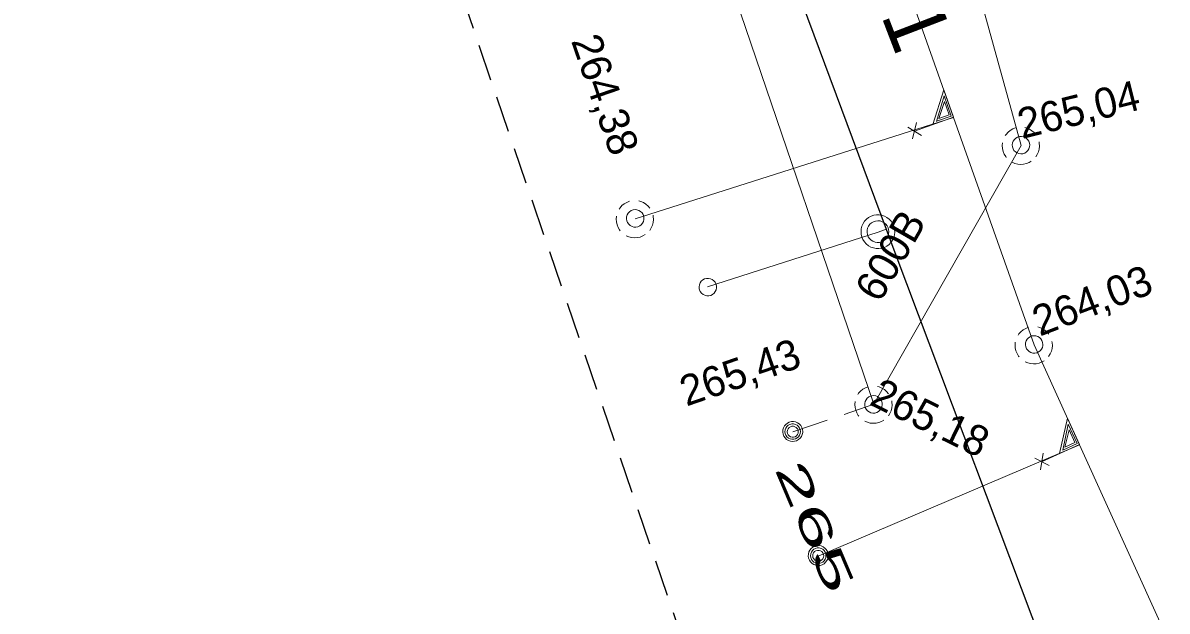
# Model space of a CAD drawing. Extents: x -732074 to -731966, y -1048695 to -1047982.
# Drawn here: x -732074 to -732043.73, y -1048462.87 to -1048447.33 of the extents above; entities that cross this region are included whole.
import ezdxf

# ---------------------------------------------------------------- set-up
doc = ezdxf.new("R2010")
doc.units = 0
doc.header["$LTSCALE"] = 0.32
doc.linetypes.add('MEDIUM_DASHED', pattern=[4.5, 3, -1.5])
doc.layers.add('1', color=7, linetype='Continuous')
for name, color, linetype, lineweight in [('18', 7, 'Continuous', 13), ('20', 7, 'Continuous', 13), ('49', 7, 'Continuous', 13), ('63', 7, 'MEDIUM_DASHED', 25), ('8', 7, 'Continuous', 13)]:
    doc.layers.add(name, color=color, linetype=linetype, lineweight=lineweight)

msp = doc.modelspace()

# ---------------------------------------------------------------- linework, layer by layer
at = {"layer": '18'}
for p, q in [((-732050.591, -1048450.086), (-732050.226, -1048450.312)), ((-732050.466, -1048450.401), (-732050.36, -1048449.97)), ((-732047.235, -1048458.835), (-732046.852, -1048459.029)), ((-732047.083, -1048459.139), (-732047.014, -1048458.7))]:
    msp.add_line(p, q, dxfattribs=at)
for points in [[(-732050.416, -1048450.195), (-732049.383, -1048449.829), (-732049.641, -1048449.102), (-732049.928, -1048450.022)], [(-732049.833, -1048449.934), (-732049.441, -1048449.795), (-732049.63, -1048449.263), (-732049.834, -1048449.935)], [(-732049.77, -1048449.862), (-732049.496, -1048449.765), (-732049.62, -1048449.415), (-732049.769, -1048449.864)], [(-732047.743, -1048450.107), (-732047.814, -1048450.135), (-732047.88, -1048450.174), (-732047.941, -1048450.222), (-732047.992, -1048450.279), (-732048.016, -1048450.313)], [(-732047.201, -1048450.29), (-732047.252, -1048450.232), (-732047.309, -1048450.182), (-732047.375, -1048450.141), (-732047.446, -1048450.112), (-732047.495, -1048450.098)], [(-732048.088, -1048450.499), (-732048.093, -1048450.576), (-732048.088, -1048450.653), (-732048.071, -1048450.728), (-732048.043, -1048450.799), (-732048.002, -1048450.865), (-732047.987, -1048450.887)], [(-732047.206, -1048450.876), (-732047.166, -1048450.811), (-732047.135, -1048450.741), (-732047.115, -1048450.666), (-732047.108, -1048450.59), (-732047.113, -1048450.513), (-732047.119, -1048450.478)], [(-732047.83, -1048451.016), (-732047.76, -1048451.047), (-732047.684, -1048451.066), (-732047.608, -1048451.073), (-732047.532, -1048451.068), (-732047.456, -1048451.051), (-732047.385, -1048451.023), (-732047.325, -1048450.988)], [(-732057.953, -1048452.047), (-732058.024, -1048452.075), (-732058.091, -1048452.114), (-732058.151, -1048452.162), (-732058.202, -1048452.219), (-732058.226, -1048452.253)], [(-732057.412, -1048452.23), (-732057.462, -1048452.172), (-732057.52, -1048452.122), (-732057.585, -1048452.081), (-732057.656, -1048452.052), (-732057.705, -1048452.038)], [(-732058.298, -1048452.439), (-732058.304, -1048452.516), (-732058.299, -1048452.593), (-732058.282, -1048452.668), (-732058.253, -1048452.739), (-732058.213, -1048452.805), (-732058.197, -1048452.827)], [(-732057.417, -1048452.816), (-732057.376, -1048452.751), (-732057.345, -1048452.681), (-732057.326, -1048452.606), (-732057.318, -1048452.53), (-732057.323, -1048452.453), (-732057.329, -1048452.418)], [(-732058.04, -1048452.956), (-732057.97, -1048452.987), (-732057.895, -1048453.006), (-732057.819, -1048453.013), (-732057.742, -1048453.008), (-732057.667, -1048452.991), (-732057.595, -1048452.963), (-732057.535, -1048452.928)], [(-732047.403, -1048455.377), (-732047.474, -1048455.405), (-732047.541, -1048455.444), (-732047.601, -1048455.492), (-732047.652, -1048455.549), (-732047.676, -1048455.583)], [(-732046.862, -1048455.56), (-732046.912, -1048455.502), (-732046.97, -1048455.452), (-732047.035, -1048455.411), (-732047.106, -1048455.382), (-732047.155, -1048455.368)], [(-732047.748, -1048455.769), (-732047.754, -1048455.846), (-732047.749, -1048455.923), (-732047.732, -1048455.998), (-732047.703, -1048456.069), (-732047.663, -1048456.135), (-732047.647, -1048456.157)], [(-732046.867, -1048456.146), (-732046.826, -1048456.081), (-732046.795, -1048456.011), (-732046.776, -1048455.936), (-732046.768, -1048455.86), (-732046.773, -1048455.783), (-732046.779, -1048455.748)], [(-732047.49, -1048456.286), (-732047.42, -1048456.317), (-732047.345, -1048456.336), (-732047.269, -1048456.343), (-732047.192, -1048456.338), (-732047.117, -1048456.321), (-732047.045, -1048456.293), (-732046.985, -1048456.258)], [(-732051.642, -1048456.947), (-732051.713, -1048456.975), (-732051.779, -1048457.014), (-732051.84, -1048457.062), (-732051.891, -1048457.119), (-732051.914, -1048457.153)], [(-732051.1, -1048457.13), (-732051.151, -1048457.072), (-732051.208, -1048457.022), (-732051.274, -1048456.981), (-732051.345, -1048456.952), (-732051.394, -1048456.938)], [(-732051.987, -1048457.339), (-732051.992, -1048457.416), (-732051.987, -1048457.493), (-732051.97, -1048457.568), (-732051.941, -1048457.639), (-732051.901, -1048457.705), (-732051.886, -1048457.727)], [(-732051.105, -1048457.716), (-732051.065, -1048457.651), (-732051.034, -1048457.581), (-732051.014, -1048457.506), (-732051.007, -1048457.43), (-732051.012, -1048457.353), (-732051.017, -1048457.318)], [(-732051.728, -1048457.856), (-732051.659, -1048457.887), (-732051.583, -1048457.906), (-732051.507, -1048457.913), (-732051.431, -1048457.908), (-732051.355, -1048457.891), (-732051.284, -1048457.863), (-732051.223, -1048457.828)], [(-732047.051, -1048458.929), (-732046.053, -1048458.475), (-732046.372, -1048457.773), (-732046.579, -1048458.714)], [(-732046.493, -1048458.619), (-732046.114, -1048458.447), (-732046.348, -1048457.933), (-732046.494, -1048458.619)], [(-732046.436, -1048458.541), (-732046.171, -1048458.421), (-732046.325, -1048458.083), (-732046.435, -1048458.543)]]:
    msp.add_lwpolyline(points, dxfattribs=at)
for points in [[(-732047.484, -1048450.364), (-732047.532, -1048450.343), (-732047.585, -1048450.334), (-732047.637, -1048450.336), (-732047.688, -1048450.351), (-732047.733, -1048450.377), (-732047.772, -1048450.412), (-732047.802, -1048450.455), (-732047.822, -1048450.504), (-732047.83, -1048450.556), (-732047.825, -1048450.609), (-732047.809, -1048450.659), (-732047.783, -1048450.703), (-732047.746, -1048450.742), (-732047.702, -1048450.77), (-732047.653, -1048450.789), (-732047.601, -1048450.794), (-732047.549, -1048450.79), (-732047.498, -1048450.772), (-732047.455, -1048450.744), (-732047.417, -1048450.707), (-732047.39, -1048450.663), (-732047.373, -1048450.612), (-732047.368, -1048450.56), (-732047.375, -1048450.508), (-732047.394, -1048450.459), (-732047.423, -1048450.415), (-732047.461, -1048450.379)], [(-732057.569, -1048452.499), (-732057.575, -1048452.447), (-732057.593, -1048452.397), (-732057.621, -1048452.353), (-732057.659, -1048452.316), (-732057.704, -1048452.289), (-732057.754, -1048452.273), (-732057.806, -1048452.268), (-732057.858, -1048452.275), (-732057.907, -1048452.294), (-732057.951, -1048452.324), (-732057.986, -1048452.363), (-732058.012, -1048452.408), (-732058.027, -1048452.459), (-732058.03, -1048452.511), (-732058.022, -1048452.563), (-732058.001, -1048452.611), (-732057.971, -1048452.654), (-732057.931, -1048452.689), (-732057.885, -1048452.713), (-732057.834, -1048452.727), (-732057.782, -1048452.729), (-732057.73, -1048452.719), (-732057.682, -1048452.697), (-732057.64, -1048452.665), (-732057.607, -1048452.625), (-732057.583, -1048452.578), (-732057.571, -1048452.527)], [(-732047.019, -1048455.829), (-732047.025, -1048455.777), (-732047.043, -1048455.727), (-732047.071, -1048455.683), (-732047.109, -1048455.646), (-732047.154, -1048455.619), (-732047.204, -1048455.603), (-732047.256, -1048455.598), (-732047.308, -1048455.605), (-732047.357, -1048455.624), (-732047.401, -1048455.654), (-732047.436, -1048455.693), (-732047.462, -1048455.738), (-732047.477, -1048455.789), (-732047.48, -1048455.841), (-732047.472, -1048455.893), (-732047.451, -1048455.941), (-732047.421, -1048455.984), (-732047.381, -1048456.019), (-732047.335, -1048456.043), (-732047.284, -1048456.057), (-732047.232, -1048456.059), (-732047.18, -1048456.049), (-732047.132, -1048456.027), (-732047.09, -1048455.995), (-732047.057, -1048455.955), (-732047.033, -1048455.908), (-732047.021, -1048455.857)], [(-732051.573, -1048457.194), (-732051.62, -1048457.217), (-732051.662, -1048457.25), (-732051.694, -1048457.291), (-732051.717, -1048457.339), (-732051.728, -1048457.39), (-732051.727, -1048457.442), (-732051.715, -1048457.493), (-732051.692, -1048457.54), (-732051.658, -1048457.58), (-732051.615, -1048457.612), (-732051.567, -1048457.633), (-732051.516, -1048457.643), (-732051.463, -1048457.641), (-732051.413, -1048457.627), (-732051.366, -1048457.602), (-732051.328, -1048457.567), (-732051.297, -1048457.525), (-732051.276, -1048457.476), (-732051.268, -1048457.424), (-732051.272, -1048457.371), (-732051.287, -1048457.322), (-732051.313, -1048457.276), (-732051.349, -1048457.237), (-732051.393, -1048457.208), (-732051.441, -1048457.19), (-732051.494, -1048457.182), (-732051.546, -1048457.187)], [(-732053.371, -1048458.129), (-732053.377, -1048458.073), (-732053.394, -1048458.02), (-732053.423, -1048457.971), (-732053.461, -1048457.93), (-732053.507, -1048457.898), (-732053.559, -1048457.876), (-732053.614, -1048457.865), (-732053.67, -1048457.867), (-732053.725, -1048457.88), (-732053.776, -1048457.905), (-732053.82, -1048457.94), (-732053.856, -1048457.983), (-732053.881, -1048458.033), (-732053.896, -1048458.088), (-732053.899, -1048458.144), (-732053.89, -1048458.199), (-732053.869, -1048458.252), (-732053.838, -1048458.298), (-732053.798, -1048458.337), (-732053.75, -1048458.367), (-732053.697, -1048458.386), (-732053.641, -1048458.393), (-732053.585, -1048458.389), (-732053.531, -1048458.372), (-732053.482, -1048458.345), (-732053.44, -1048458.307), (-732053.407, -1048458.262), (-732053.384, -1048458.211), (-732053.372, -1048458.156)], [(-732053.43, -1048458.132), (-732053.436, -1048458.083), (-732053.454, -1048458.037), (-732053.482, -1048457.996), (-732053.519, -1048457.963), (-732053.563, -1048457.941), (-732053.611, -1048457.929), (-732053.66, -1048457.929), (-732053.708, -1048457.941), (-732053.752, -1048457.964), (-732053.789, -1048457.997), (-732053.817, -1048458.038), (-732053.834, -1048458.085), (-732053.84, -1048458.134), (-732053.833, -1048458.183), (-732053.815, -1048458.229), (-732053.787, -1048458.269), (-732053.75, -1048458.302), (-732053.706, -1048458.324), (-732053.657, -1048458.336), (-732053.608, -1048458.335), (-732053.56, -1048458.323), (-732053.517, -1048458.299), (-732053.48, -1048458.266), (-732053.452, -1048458.225), (-732053.436, -1048458.178)], [(-732053.489, -1048458.136), (-732053.495, -1048458.094), (-732053.512, -1048458.056), (-732053.54, -1048458.025), (-732053.575, -1048458.002), (-732053.615, -1048457.991), (-732053.657, -1048457.991), (-732053.697, -1048458.003), (-732053.732, -1048458.026), (-732053.759, -1048458.058), (-732053.776, -1048458.096), (-732053.781, -1048458.137), (-732053.775, -1048458.179), (-732053.757, -1048458.216), (-732053.729, -1048458.248), (-732053.693, -1048458.27), (-732053.653, -1048458.281), (-732053.611, -1048458.28), (-732053.571, -1048458.267), (-732053.537, -1048458.244), (-732053.51, -1048458.211), (-732053.494, -1048458.173)], [(-732052.696, -1048461.407), (-732052.701, -1048461.351), (-732052.718, -1048461.298), (-732052.747, -1048461.249), (-732052.786, -1048461.208), (-732052.831, -1048461.176), (-732052.884, -1048461.154), (-732052.939, -1048461.143), (-732052.995, -1048461.145), (-732053.049, -1048461.158), (-732053.1, -1048461.183), (-732053.145, -1048461.218), (-732053.181, -1048461.261), (-732053.206, -1048461.311), (-732053.221, -1048461.366), (-732053.223, -1048461.422), (-732053.215, -1048461.477), (-732053.194, -1048461.53), (-732053.163, -1048461.576), (-732053.122, -1048461.615), (-732053.075, -1048461.645), (-732053.022, -1048461.664), (-732052.966, -1048461.671), (-732052.909, -1048461.667), (-732052.855, -1048461.65), (-732052.806, -1048461.623), (-732052.765, -1048461.585), (-732052.732, -1048461.54), (-732052.708, -1048461.489), (-732052.696, -1048461.434)], [(-732052.755, -1048461.41), (-732052.761, -1048461.361), (-732052.779, -1048461.315), (-732052.806, -1048461.274), (-732052.843, -1048461.241), (-732052.887, -1048461.219), (-732052.936, -1048461.207), (-732052.985, -1048461.207), (-732053.032, -1048461.219), (-732053.076, -1048461.242), (-732053.114, -1048461.275), (-732053.142, -1048461.316), (-732053.159, -1048461.363), (-732053.164, -1048461.412), (-732053.157, -1048461.461), (-732053.14, -1048461.507), (-732053.112, -1048461.547), (-732053.075, -1048461.58), (-732053.031, -1048461.602), (-732052.982, -1048461.614), (-732052.933, -1048461.613), (-732052.885, -1048461.601), (-732052.842, -1048461.577), (-732052.804, -1048461.544), (-732052.777, -1048461.503), (-732052.761, -1048461.456)], [(-732052.814, -1048461.414), (-732052.82, -1048461.372), (-732052.837, -1048461.334), (-732052.865, -1048461.303), (-732052.899, -1048461.28), (-732052.94, -1048461.269), (-732052.982, -1048461.269), (-732053.022, -1048461.281), (-732053.056, -1048461.304), (-732053.083, -1048461.336), (-732053.1, -1048461.374), (-732053.105, -1048461.415), (-732053.1, -1048461.457), (-732053.081, -1048461.494), (-732053.054, -1048461.526), (-732053.017, -1048461.548), (-732052.978, -1048461.559), (-732052.936, -1048461.558), (-732052.896, -1048461.545), (-732052.862, -1048461.522), (-732052.835, -1048461.489), (-732052.819, -1048461.451)]]:
    msp.add_lwpolyline(points, close=True, dxfattribs=at)
at = {"layer": '20'}
for p, q in [((-732047.59, -1048450.57), (-732053.92, -1048427.8)), ((-732047.59, -1048450.57), (-732053.92, -1048427.8)), ((-732051.489, -1048457.41), (-732060.89, -1048429.86)), ((-732051.489, -1048457.41), (-732060.89, -1048429.86)), ((-732051.489, -1048457.41), (-732047.59, -1048450.57)), ((-732051.489, -1048457.41), (-732047.59, -1048450.57))]:
    msp.add_line(p, q, dxfattribs=at)
for points in [[(-732047.25, -1048455.84), (-732049.379, -1048449.833), (-732051.352, -1048444.273), (-732055.579, -1048432.35)], [(-732047.25, -1048455.84), (-732049.379, -1048449.833), (-732051.352, -1048444.273), (-732055.579, -1048432.35)], [(-732034.829, -1048483.16), (-732035.513, -1048481.657), (-732046.05, -1048458.48), (-732047.25, -1048455.84)], [(-732034.829, -1048483.16), (-732035.513, -1048481.657), (-732046.05, -1048458.48), (-732047.25, -1048455.84)]]:
    msp.add_lwpolyline(points, dxfattribs=at)
at = {"layer": '49'}
for p, q in [((-732057.8, -1048452.51), (-732049.379, -1048449.833)), ((-732057.8, -1048452.51), (-732049.379, -1048449.833)), ((-732052.96, -1048461.42), (-732046.05, -1048458.48)), ((-732052.96, -1048461.42), (-732046.05, -1048458.48))]:
    msp.add_line(p, q, dxfattribs=at)
at = {"layer": '49', "linetype": 'MEDIUM_DASHED'}
msp.add_line((-732053.635, -1048458.142), (-732051.489, -1048457.41), dxfattribs=at)
msp.add_line((-732053.635, -1048458.142), (-732051.489, -1048457.41), dxfattribs=at)
at = {"layer": '63'}
msp.add_lwpolyline([(-732022.871, -1048561.909), (-732073.995, -1048412.717), (-732073.996, -1048412.715), (-732073.996, -1048412.713), (-732069.268, -1048320.574)], dxfattribs=at)
at = {"layer": '8'}
for p, q in [((-732051.16, -1048452.78), (-732051.379, -1048452.861)), ((-732051.379, -1048452.861), (-732055.886, -1048454.305))]:
    msp.add_line(p, q, dxfattribs=at)
at = {"layer": '8', "lineweight": 25}
msp.add_lwpolyline([(-732060.37, -1048418.12), (-732059.43, -1048430.6), (-732057.43, -1048436.03), (-732055.16, -1048442.06), (-732051.16, -1048452.78), (-732050.93, -1048453.401), (-732046.69, -1048464.651), (-732045.92, -1048466.511), (-732044.12, -1048470.56)], dxfattribs=at)
at = {"layer": '8'}
for points in [[(-732050.962, -1048452.697), (-732050.993, -1048452.63), (-732051.034, -1048452.57), (-732051.084, -1048452.517), (-732051.142, -1048452.473), (-732051.207, -1048452.438), (-732051.276, -1048452.415), (-732051.348, -1048452.404), (-732051.422, -1048452.404), (-732051.494, -1048452.417), (-732051.564, -1048452.441), (-732051.628, -1048452.476), (-732051.685, -1048452.522), (-732051.734, -1048452.574), (-732051.775, -1048452.636), (-732051.805, -1048452.703), (-732051.823, -1048452.774), (-732051.829, -1048452.847), (-732051.824, -1048452.92), (-732051.806, -1048452.991), (-732051.778, -1048453.058), (-732051.738, -1048453.12), (-732051.69, -1048453.174), (-732051.632, -1048453.221), (-732051.569, -1048453.256), (-732051.5, -1048453.281), (-732051.428, -1048453.294), (-732051.355, -1048453.296), (-732051.282, -1048453.286), (-732051.212, -1048453.264), (-732051.147, -1048453.23), (-732051.088, -1048453.187), (-732051.037, -1048453.134), (-732050.995, -1048453.074), (-732050.964, -1048453.008), (-732050.944, -1048452.937), (-732050.935, -1048452.865), (-732050.939, -1048452.792), (-732050.954, -1048452.721)], [(-732051.113, -1048452.752), (-732051.139, -1048452.699), (-732051.175, -1048452.653), (-732051.219, -1048452.615), (-732051.27, -1048452.587), (-732051.326, -1048452.568), (-732051.384, -1048452.563), (-732051.442, -1048452.569), (-732051.499, -1048452.588), (-732051.549, -1048452.617), (-732051.593, -1048452.656), (-732051.628, -1048452.703), (-732051.653, -1048452.755), (-732051.666, -1048452.812), (-732051.668, -1048452.872), (-732051.658, -1048452.929), (-732051.636, -1048452.983), (-732051.603, -1048453.032), (-732051.561, -1048453.073), (-732051.512, -1048453.104), (-732051.457, -1048453.126), (-732051.4, -1048453.135), (-732051.341, -1048453.133), (-732051.284, -1048453.118), (-732051.232, -1048453.093), (-732051.185, -1048453.058), (-732051.147, -1048453.013), (-732051.119, -1048452.961), (-732051.102, -1048452.906), (-732051.096, -1048452.848), (-732051.103, -1048452.79)], [(-732056.101, -1048454.384), (-732056.08, -1048454.431), (-732056.048, -1048454.474), (-732056.007, -1048454.507), (-732055.96, -1048454.531), (-732055.909, -1048454.543), (-732055.856, -1048454.543), (-732055.805, -1048454.532), (-732055.758, -1048454.509), (-732055.717, -1048454.476), (-732055.684, -1048454.434), (-732055.663, -1048454.387), (-732055.652, -1048454.336), (-732055.653, -1048454.283), (-732055.666, -1048454.232), (-732055.689, -1048454.185), (-732055.724, -1048454.146), (-732055.765, -1048454.114), (-732055.814, -1048454.093), (-732055.865, -1048454.084), (-732055.918, -1048454.086), (-732055.968, -1048454.1), (-732056.015, -1048454.125), (-732056.054, -1048454.161), (-732056.084, -1048454.204), (-732056.103, -1048454.252), (-732056.112, -1048454.304), (-732056.108, -1048454.356)]]:
    msp.add_lwpolyline(points, close=True, dxfattribs=at)

# ---------------------------------------------------------------- texts
at = {"layer": '1'}
for s, height, rotation, p in [('1991', 1.6, 291, (-732052.588, -1048443.793)), ('264,38', 0.8, 289, (-732059.503, -1048447.805)), ('265,04', 0.8, 14, (-732047.571, -1048450.404)), ('600B', 0.8, 60, (-732051.333, -1048454.757)), ('264,03', 0.8, 21, (-732047.101, -1048455.624)), ('265,43', 0.8, 19, (-732056.448, -1048457.472)), ('265,18', 0.8, 334, (-732051.638, -1048457.405))]:
    msp.add_text(s, height=height, rotation=rotation, dxfattribs=at).set_placement(p)
at = {"layer": '1', "width": 2.05}
msp.add_text('265 ', height=0.8, rotation=293, dxfattribs=at).set_placement((-732054.127, -1048459.111))

doc.saveas('drawing.dxf')
